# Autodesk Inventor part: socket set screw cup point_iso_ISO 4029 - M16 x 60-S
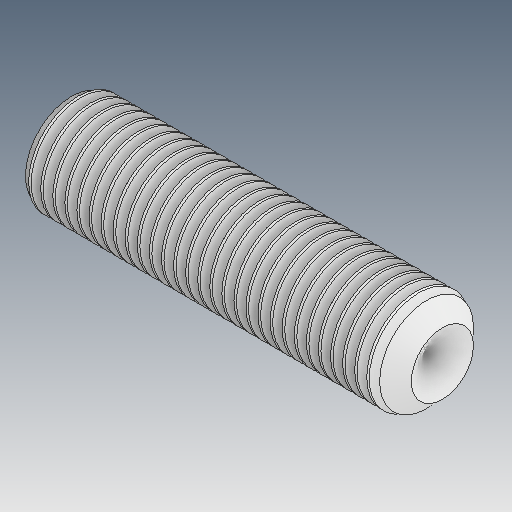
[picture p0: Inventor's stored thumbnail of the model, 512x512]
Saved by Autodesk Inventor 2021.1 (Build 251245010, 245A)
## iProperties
Created: 2021-05
Part Number: socket set screw cup point_iso_ISO 4029 - M16 x 60-S
Material: Ogólny
Document SubType Name: Modeling
Designer: user
Density: 1 g/cm^3
Appearance: Domyślna
Author: user
Revision Number: ÈÎºÎ
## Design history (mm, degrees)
feature "ÊäÈë1"
node "Bryła1"
